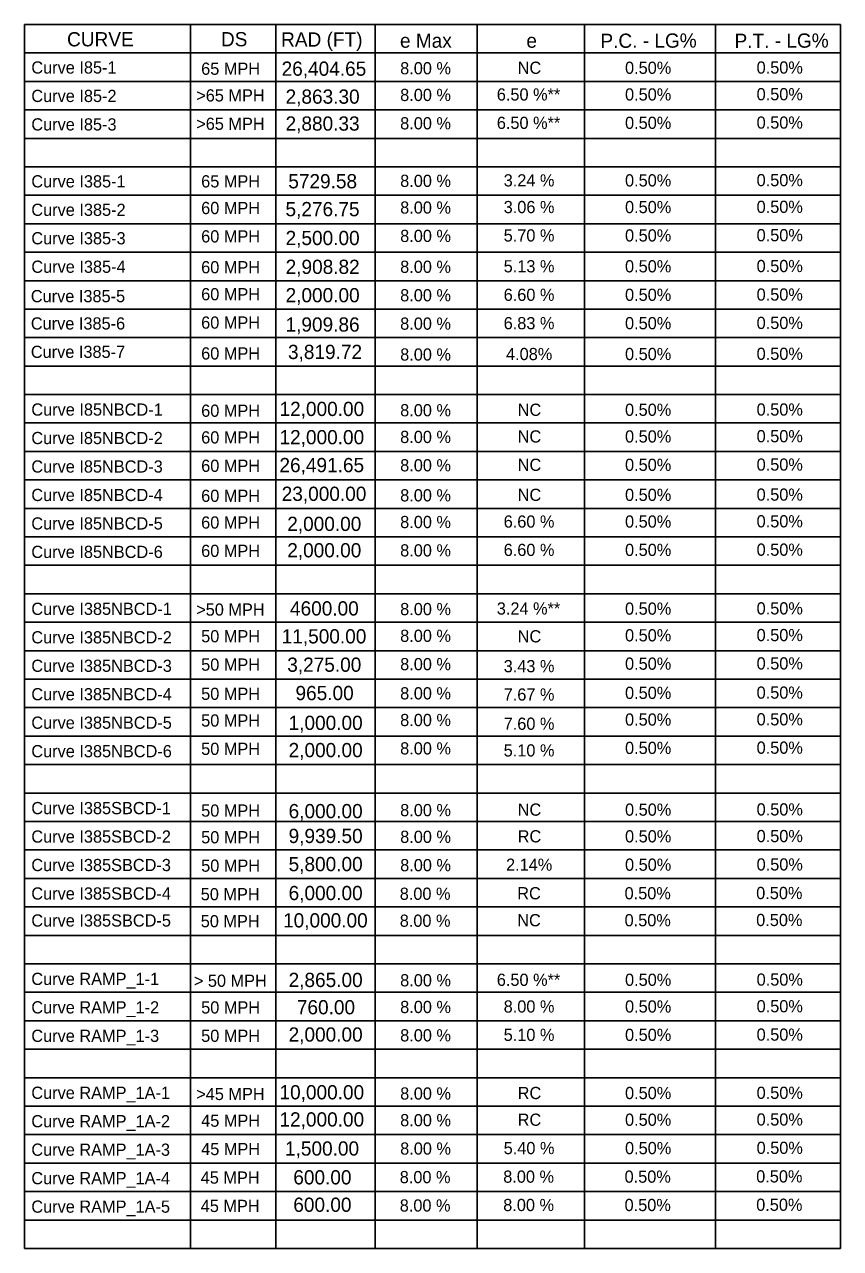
# Model space of a CAD drawing. Extents: x 1609180 to 1612299, y 1092317 to 1096201.
# Drawn here: x 1609692 to 1610094, y 1095436 to 1096038 of the extents above; entities that cross this region are included whole.
import ezdxf

# ---------------------------------------------------------------- set-up
doc = ezdxf.new("R2010")
doc.units = 0
doc.layers.add('RD_HC_Data_50', color=7, linetype='Continuous')
doc.layers.add('RD_SHT_TX', color=7, linetype='Continuous')

msp = doc.modelspace()

# ---------------------------------------------------------------- linework, layer by layer
at = {"layer": 'RD_SHT_TX'}
for p, q in [((1609692.37, 1096037.78), (1609692.37, 1095435.78)), ((1609692.37, 1096037.78), (1610093.83, 1096037.78)), ((1609774.01, 1096037.78), (1609774.01, 1095435.78)), ((1609816.11, 1096037.78), (1609816.11, 1095435.78)), ((1609864.91, 1096037.78), (1609864.91, 1095435.78)), ((1609915.04, 1096037.78), (1609915.04, 1095435.78)), ((1609967.94, 1096037.78), (1609967.94, 1095435.78)), ((1610032.32, 1096037.78), (1610032.32, 1095435.78)), ((1610093.83, 1096037.78), (1610093.83, 1095435.78)), ((1609692.37, 1096023.78), (1610093.83, 1096023.78)), ((1609692.37, 1096009.78), (1610093.83, 1096009.78)), ((1609692.37, 1095995.78), (1610093.83, 1095995.78)), ((1609692.37, 1095981.78), (1610093.83, 1095981.78)), ((1609692.37, 1095967.78), (1610093.83, 1095967.78)), ((1609692.37, 1095953.78), (1610093.83, 1095953.78)), ((1609692.37, 1095939.78), (1610093.83, 1095939.78)), ((1609692.37, 1095925.78), (1610093.83, 1095925.78)), ((1609692.37, 1095911.78), (1610093.83, 1095911.78)), ((1609692.37, 1095897.78), (1610093.83, 1095897.78)), ((1609692.37, 1095883.78), (1610093.83, 1095883.78)), ((1609692.37, 1095869.78), (1610093.83, 1095869.78)), ((1609692.37, 1095855.78), (1610093.83, 1095855.78)), ((1609692.37, 1095841.78), (1610093.83, 1095841.78)), ((1609692.37, 1095827.78), (1610093.83, 1095827.78)), ((1609692.37, 1095813.78), (1610093.83, 1095813.78)), ((1609692.37, 1095799.78), (1610093.83, 1095799.78)), ((1609692.37, 1095785.78), (1610093.83, 1095785.78)), ((1609692.37, 1095771.78), (1610093.83, 1095771.78)), ((1609692.37, 1095757.78), (1610093.83, 1095757.78)), ((1609692.37, 1095743.78), (1610093.83, 1095743.78)), ((1609692.37, 1095729.78), (1610093.83, 1095729.78)), ((1609692.37, 1095715.78), (1610093.83, 1095715.78)), ((1609692.37, 1095701.78), (1610093.83, 1095701.78)), ((1609692.37, 1095687.78), (1610093.83, 1095687.78)), ((1609692.37, 1095673.78), (1610093.83, 1095673.78)), ((1609692.37, 1095659.78), (1610093.83, 1095659.78)), ((1609692.37, 1095645.78), (1610093.83, 1095645.78)), ((1609692.37, 1095631.78), (1610093.83, 1095631.78)), ((1609692.37, 1095617.78), (1610093.83, 1095617.78)), ((1609692.37, 1095603.78), (1610093.83, 1095603.78)), ((1609692.37, 1095589.78), (1610093.83, 1095589.78)), ((1609692.37, 1095575.78), (1610093.83, 1095575.78)), ((1609692.37, 1095561.78), (1610093.83, 1095561.78)), ((1609692.37, 1095547.78), (1610093.83, 1095547.78)), ((1609692.37, 1095533.78), (1610093.83, 1095533.78)), ((1609692.37, 1095519.78), (1610093.83, 1095519.78)), ((1609692.37, 1095505.78), (1610093.83, 1095505.78)), ((1609692.37, 1095491.78), (1610093.83, 1095491.78)), ((1609692.37, 1095477.78), (1610093.83, 1095477.78)), ((1609692.37, 1095463.78), (1610093.83, 1095463.78)), ((1609692.37, 1095449.78), (1610093.83, 1095449.78)), ((1609692.37, 1095435.78), (1610093.83, 1095435.78))]:
    msp.add_line(p, q, dxfattribs=at)

# ---------------------------------------------------------------- texts
at = {"layer": 'RD_HC_Data_50'}
for s, p in [('P.C. - LG%', (1609975.73, 1096026.23)), ('P.T. - LG%', (1610041.71, 1096026.23))]:
    msp.add_text(s, height=7, rotation=0.2225, dxfattribs=at).set_placement(p)
for s, p in [('8.00 %', (1609877.2, 1096013.26)), ('NC', (1609935.01, 1096013.5)), ('0.50%', (1609987.82, 1096013.5)), ('0.50%', (1610052.55, 1096013.61)), ('65 MPH', (1609779.3, 1096013.03)), ('>65 MPH', (1609776.86, 1095999.9)), ('8.00 %', (1609877.2, 1096000.13)), ('6.50 %**', (1609924.74, 1096000.37)), ('0.50%', (1609987.82, 1096000.37)), ('0.50%', (1610052.55, 1096000.49)), ('>65 MPH', (1609776.86, 1095985.95)), ('8.00 %', (1609877.2, 1095986.19)), ('6.50 %**', (1609924.74, 1095986.42)), ('0.50%', (1609987.82, 1095986.42)), ('0.50%', (1610052.55, 1095986.54)), ('65 MPH', (1609779.3, 1095957.64)), ('8.00 %', (1609877.2, 1095957.88)), ('3.24 %', (1609928.12, 1095958.11)), ('0.50%', (1609987.82, 1095958.11)), ('0.50%', (1610052.55, 1095958.23)), ('60 MPH', (1609779.3, 1095944.52)), ('8.00 %', (1609877.2, 1095944.75)), ('3.06 %', (1609928.12, 1095944.99)), ('0.50%', (1609987.82, 1095944.99)), ('0.50%', (1610052.55, 1095945.1)), ('60 MPH', (1609779.3, 1095930.57)), ('8.00 %', (1609877.2, 1095930.8)), ('5.70 %', (1609928.12, 1095931.04)), ('0.50%', (1609987.82, 1095931.04)), ('0.50%', (1610052.55, 1095931.15)), ('60 MPH', (1609779.3, 1095915.39)), ('8.00 %', (1609877.2, 1095915.62)), ('5.13 %', (1609928.12, 1095915.86)), ('0.50%', (1609987.82, 1095915.86)), ('0.50%', (1610052.55, 1095915.98)), ('60 MPH', (1609779.3, 1095902.12)), ('8.00 %', (1609877.2, 1095901.61)), ('6.60 %', (1609928.12, 1095901.84)), ('0.50%', (1609987.82, 1095901.84)), ('0.50%', (1610052.55, 1095901.96)), ('60 MPH', (1609779.3, 1095888.17)), ('8.00 %', (1609877.2, 1095887.66)), ('6.83 %', (1609928.12, 1095887.89)), ('0.50%', (1609987.82, 1095887.89)), ('0.50%', (1610052.55, 1095888.01)), ('60 MPH', (1609779.3, 1095873)), ('8.00 %', (1609877.2, 1095872.48)), ('4.08%', (1609929.28, 1095872.71)), ('0.50%', (1609987.82, 1095872.71)), ('0.50%', (1610052.55, 1095872.83)), ('60 MPH', (1609779.3, 1095844.83)), ('8.00 %', (1609877.2, 1095845.06)), ('NC', (1609935.01, 1095845.3)), ('0.50%', (1609987.82, 1095845.3)), ('0.50%', (1610052.55, 1095845.41)), ('60 MPH', (1609779.3, 1095831.7)), ('8.00 %', (1609877.2, 1095831.93)), ('NC', (1609935.01, 1095832.17)), ('0.50%', (1609987.82, 1095832.17)), ('0.50%', (1610052.55, 1095832.29)), ('60 MPH', (1609779.3, 1095817.75)), ('8.00 %', (1609877.2, 1095817.99)), ('NC', (1609935.01, 1095818.22)), ('0.50%', (1609987.82, 1095818.22)), ('0.50%', (1610052.55, 1095818.34)), ('60 MPH', (1609779.3, 1095802.98)), ('8.00 %', (1609877.2, 1095803.22)), ('NC', (1609935.01, 1095803.45)), ('0.50%', (1609987.82, 1095803.45)), ('0.50%', (1610052.55, 1095803.57)), ('0.50%', (1610052.55, 1095790.44)), ('60 MPH', (1609779.3, 1095789.85)), ('8.00 %', (1609877.2, 1095790.09)), ('6.60 %', (1609928.12, 1095790.32)), ('0.50%', (1609987.82, 1095790.32)), ('60 MPH', (1609779.3, 1095775.91)), ('8.00 %', (1609877.2, 1095776.14)), ('6.60 %', (1609928.12, 1095776.38)), ('0.50%', (1609987.82, 1095776.38)), ('0.50%', (1610052.55, 1095776.49)), ('>50 MPH', (1609776.86, 1095747.04)), ('8.00 %', (1609877.2, 1095747.27)), ('3.24 %**', (1609924.74, 1095747.56)), ('0.50%', (1609987.82, 1095747.5)), ('0.50%', (1610052.55, 1095747.62)), ('50 MPH', (1609779.3, 1095733.91)), ('8.00 %', (1609877.2, 1095734.14)), ('NC', (1609935.01, 1095733.87)), ('0.50%', (1609987.82, 1095734.38)), ('0.50%', (1610052.55, 1095734.49)), ('50 MPH', (1609779.3, 1095719.96)), ('8.00 %', (1609877.2, 1095720.19)), ('3.43 %', (1609928.12, 1095719.2)), ('0.50%', (1609987.82, 1095720.43)), ('0.50%', (1610052.55, 1095720.55)), ('0.50%', (1610052.55, 1095706.19)), ('50 MPH', (1609779.3, 1095705.6)), ('8.00 %', (1609877.2, 1095705.84)), ('7.67 %', (1609928.12, 1095705.25)), ('0.50%', (1609987.82, 1095706.07)), ('50 MPH', (1609779.3, 1095692.47)), ('8.00 %', (1609877.2, 1095692.71)), ('7.60 %', (1609928.12, 1095690.89)), ('0.50%', (1609987.82, 1095692.94)), ('0.50%', (1610052.55, 1095693.06)), ('50 MPH', (1609779.3, 1095678.53)), ('8.00 %', (1609877.2, 1095678.76)), ('5.10 %', (1609928.12, 1095677.76)), ('0.50%', (1609987.82, 1095678.99)), ('0.50%', (1610052.55, 1095679.11)), ('50 MPH', (1609779.3, 1095648.17)), ('8.00 %', (1609877.2, 1095648.4)), ('NC', (1609935.01, 1095648.64)), ('0.50%', (1609987.82, 1095648.64)), ('0.50%', (1610052.55, 1095648.75)), ('50 MPH', (1609779.3, 1095635.04)), ('8.00 %', (1609877.2, 1095635.27)), ('RC', (1609935.01, 1095635.51)), ('0.50%', (1609987.82, 1095635.51)), ('0.50%', (1610052.55, 1095635.63)), ('50 MPH', (1609779.3, 1095621.09)), ('8.00 %', (1609877.2, 1095621.33)), ('2.14%', (1609929.28, 1095621.56)), ('0.50%', (1609987.82, 1095621.56)), ('0.50%', (1610052.55, 1095621.68)), ('50 MPH', (1609779.09, 1095607.04)), ('8.00 %', (1609876.99, 1095607.27)), ('RC', (1609934.8, 1095607.51)), ('0.50%', (1609987.6, 1095607.51)), ('0.50%', (1610052.34, 1095607.62)), ('50 MPH', (1609779.09, 1095593.78)), ('8.00 %', (1609876.99, 1095594.01)), ('NC', (1609934.8, 1095594.25)), ('0.50%', (1609987.6, 1095594.25)), ('0.50%', (1610052.34, 1095594.36)), ('> 50 MPH', (1609775.69, 1095564.48)), ('8.00 %', (1609877.2, 1095564.71)), ('6.50 %**', (1609924.74, 1095564.95)), ('0.50%', (1609987.82, 1095564.95)), ('0.50%', (1610052.55, 1095565.06)), ('50 MPH', (1609779.3, 1095551.35)), ('8.00 %', (1609877.2, 1095551.58)), ('8.00 %', (1609928.12, 1095551.82)), ('0.50%', (1609987.82, 1095551.82)), ('0.50%', (1610052.55, 1095551.94)), ('8.00 %', (1609877.2, 1095537.64)), ('5.10 %', (1609928.12, 1095537.87)), ('0.50%', (1609987.82, 1095537.87)), ('0.50%', (1610052.55, 1095537.99)), ('50 MPH', (1609779.3, 1095537.4)), ('>45 MPH', (1609776.86, 1095508.79)), ('8.00 %', (1609877.2, 1095509.02)), ('RC', (1609935.01, 1095509.26)), ('0.50%', (1609987.82, 1095509.26)), ('0.50%', (1610052.55, 1095509.37)), ('45 MPH', (1609779.3, 1095495.66)), ('8.00 %', (1609877.2, 1095495.89)), ('RC', (1609935.01, 1095496.13)), ('0.50%', (1609987.82, 1095496.13)), ('0.50%', (1610052.55, 1095496.25)), ('45 MPH', (1609779.3, 1095481.71)), ('8.00 %', (1609877.2, 1095481.95)), ('5.40 %', (1609928.12, 1095482.18)), ('0.50%', (1609987.82, 1095482.18)), ('0.50%', (1610052.55, 1095482.3)), ('45 MPH', (1609779.09, 1095467.67)), ('8.00 %', (1609876.99, 1095467.91)), ('8.00 %', (1609927.9, 1095468.14)), ('0.50%', (1609987.6, 1095468.14)), ('0.50%', (1610052.34, 1095468.26)), ('45 MPH', (1609779.09, 1095453.73)), ('8.00 %', (1609876.99, 1095453.96)), ('8.00 %', (1609927.9, 1095454.19)), ('0.50%', (1609987.6, 1095454.19)), ('0.50%', (1610052.34, 1095454.31))]:
    msp.add_text(s, height=6, dxfattribs=at).set_placement(p)
at = {"layer": 'RD_SHT_TX'}
for s, height, p in [('CURVE', 7, (1609713.33, 1096027.01)), ('DS', 7, (1609789.03, 1096027.04)), ('RAD (FT)', 7, (1609818.64, 1096026.9)), ('e Max', 7, (1609877.1, 1096026.33)), ('e', 7, (1609939.28, 1096026.33)), ('Curve I85-1                ', 6, (1609695.75, 1096013.64)), ('26,404.65', 7, (1609818.87, 1096012.55)), ('Curve I85-2                ', 6, (1609695.75, 1095999.64)), ('2,863.30', 7, (1609820.82, 1095998.81)), ('Curve I85-3                ', 6, (1609695.75, 1095985.64)), ('2,880.33', 7, (1609820.81, 1095985.56)), ('Curve I385-1               ', 6, (1609695.75, 1095957.64)), ('5729.58', 7, (1609822.16, 1095957.19)), ('Curve I385-2               ', 6, (1609695.75, 1095943.64)), ('5,276.75', 7, (1609820.78, 1095943.47)), ('Curve I385-3               ', 6, (1609695.75, 1095929.64)), ('2,500.00', 7, (1609820.82, 1095929.28)), ('Curve I385-4               ', 6, (1609695.75, 1095915.64)), ('2,908.82', 7, (1609820.85, 1095915.1)), ('Curve I385-5               ', 6, (1609695.51, 1095901.18)), ('2,000.00', 7, (1609820.82, 1095901.15)), ('Curve I385-6               ', 6, (1609695.51, 1095887.75)), ('1,909.86', 7, (1609820.81, 1095886.73)), ('Curve I385-7               ', 6, (1609695.51, 1095873.79)), ('3,819.72', 7, (1609822.01, 1095873.24)), ('Curve I85NBCD-1            ', 6, (1609695.75, 1095845.39)), ('12,000.00', 7, (1609817.85, 1095845.21)), ('Curve I85NBCD-2            ', 6, (1609695.75, 1095831.39)), ('12,000.00', 7, (1609817.85, 1095831.31)), ('Curve I85NBCD-3            ', 6, (1609695.75, 1095817.39)), ('26,491.65', 7, (1609817.81, 1095817.59)), ('Curve I85NBCD-4            ', 6, (1609695.75, 1095803.39)), ('23,000.00', 7, (1609818.92, 1095803.47)), ('Curve I85NBCD-5            ', 6, (1609695.75, 1095789.39)), ('2,000.00', 7, (1609821.64, 1095788.67)), ('Curve I85NBCD-6            ', 6, (1609695.75, 1095775.39)), ('2,000.00', 7, (1609821.64, 1095775.7)), ('Curve I385NBCD-1           ', 6, (1609695.75, 1095747.39)), ('4600.00', 7, (1609822.99, 1095747.1)), ('Curve I385NBCD-2           ', 6, (1609695.75, 1095733.39)), ('11,500.00', 7, (1609818.92, 1095733.38)), ('Curve I385NBCD-3           ', 6, (1609695.75, 1095719.39)), ('3,275.00', 7, (1609821.64, 1095719.42)), ('965.00', 7, (1609825.71, 1095705.47)), ('Curve I385NBCD-4           ', 6, (1609695.75, 1095705.39)), ('Curve I385NBCD-5           ', 6, (1609695.75, 1095691.39)), ('1,000.00', 7, (1609822.31, 1095690.82)), ('Curve I385NBCD-6           ', 6, (1609695.75, 1095677.39)), ('2,000.00', 7, (1609822.31, 1095677.41)), ('Curve I385SBCD-1           ', 6, (1609695.75, 1095649.39)), ('6,000.00', 7, (1609822.31, 1095647.4)), ('Curve I385SBCD-2           ', 6, (1609695.75, 1095635.39)), ('9,939.50', 7, (1609822.31, 1095635.19)), ('5,800.00', 7, (1609822.31, 1095621.35)), ('Curve I385SBCD-3           ', 6, (1609695.75, 1095621.39)), ('Curve I385SBCD-4           ', 6, (1609695.75, 1095607.39)), ('6,000.00', 7, (1609822.31, 1095607.11)), ('Curve I385SBCD-5           ', 6, (1609695.75, 1095594.12)), ('10,000.00', 7, (1609819.59, 1095593.68)), ('Curve RAMP_1-1             ', 6, (1609695.75, 1095565.39)), ('2,865.00', 7, (1609822.31, 1095564.38)), ('Curve RAMP_1-2             ', 6, (1609695.75, 1095551.39)), ('760.00', 7, (1609826.38, 1095550.95)), ('2,000.00', 7, (1609822.31, 1095537.53)), ('Curve RAMP_1-3             ', 6, (1609695.75, 1095537.39)), ('Curve RAMP_1A-1            ', 6, (1609695.75, 1095509.39)), ('10,000.00', 7, (1609817.83, 1095509.13)), ('12,000.00', 7, (1609817.83, 1095495.77)), ('Curve RAMP_1A-2            ', 6, (1609695.75, 1095495.39)), ('Curve RAMP_1A-3            ', 6, (1609695.75, 1095481.39)), ('1,500.00', 7, (1609820.55, 1095481.48)), ('Curve RAMP_1A-4            ', 6, (1609695.75, 1095467.39)), ('600.00', 7, (1609824.62, 1095467.3)), ('Curve RAMP_1A-5            ', 6, (1609695.75, 1095453.39)), ('600.00', 7, (1609824.62, 1095453.81))]:
    msp.add_text(s, height=height, dxfattribs=at).set_placement(p)

doc.saveas('drawing.dxf')
